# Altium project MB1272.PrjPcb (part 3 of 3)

## Sheet USB_Host_Hub&TypeC_DRP.SchDoc: USB_Host_Hub&TypeC_DRP
size A3; DocumentNumber: MB1272; Revision: A-01; SheetNumber: 6; SheetTotal: 15; Project: STM32MP15-DISCO PI
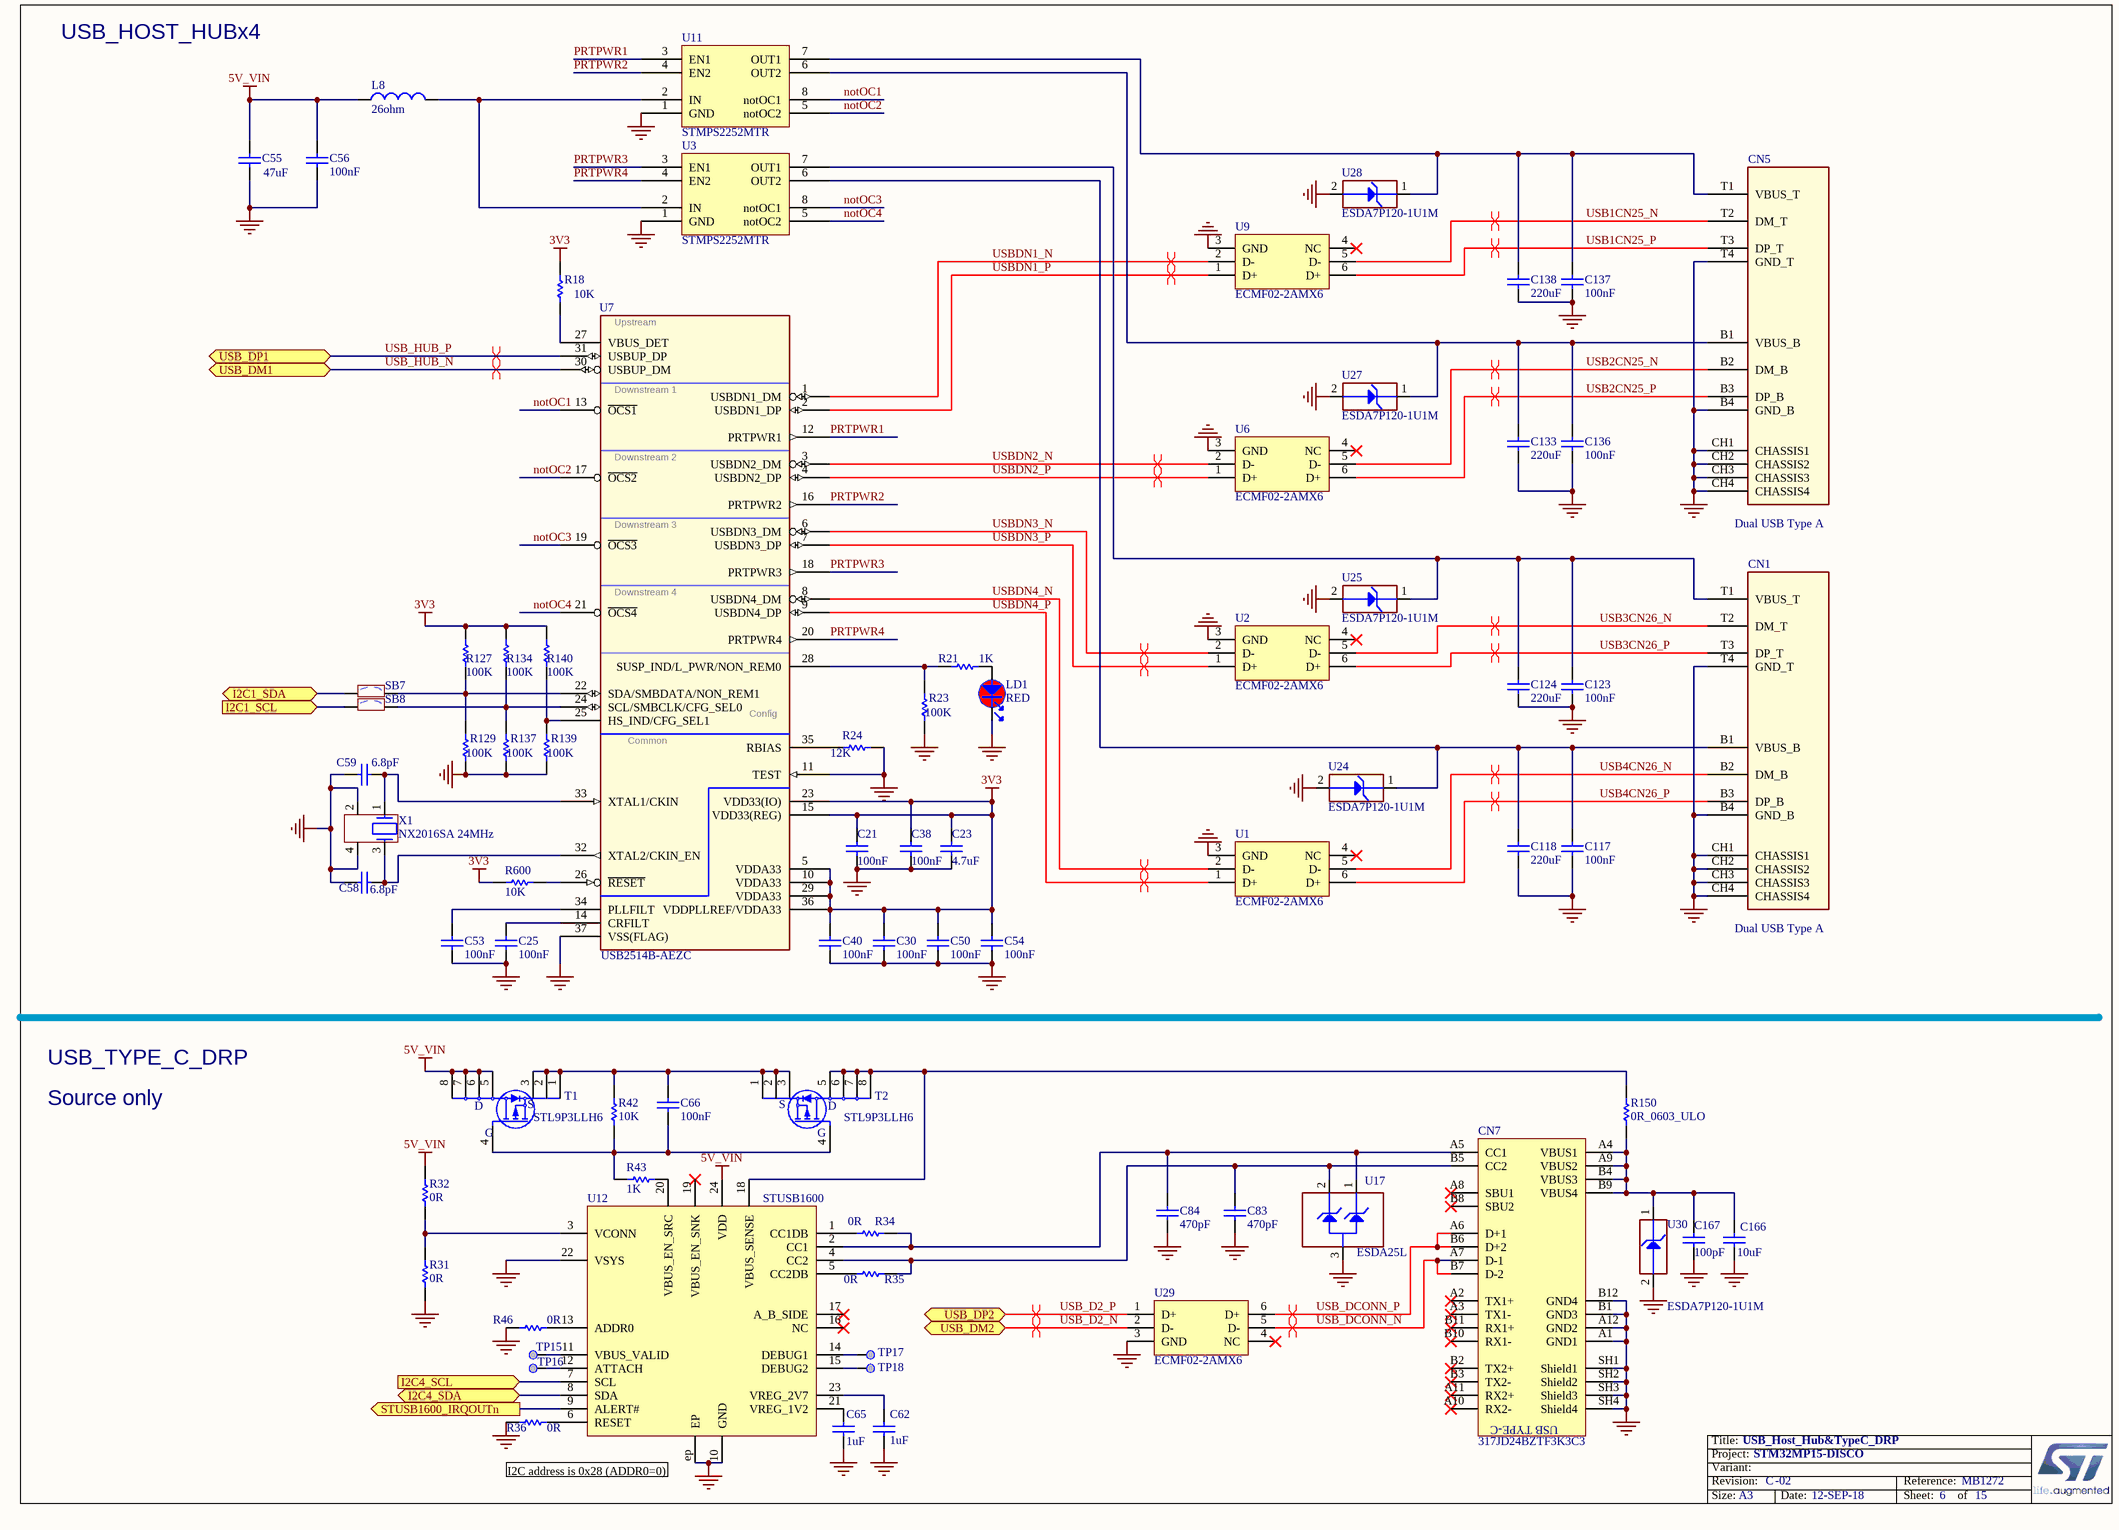
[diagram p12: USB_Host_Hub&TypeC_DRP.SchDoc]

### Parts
C21  value 100nF  [C0402]  (hidden comment: Capacitor)
C23  value 4.7uF  [C0402]  (hidden comment: Capacitor)
C25  value 100nF  [C0402]  (hidden comment: Capacitor)
C30  value 100nF  [C0402]  (hidden comment: Capacitor)
C38  value 100nF  [C0402]  (hidden comment: Capacitor)
C40  value 100nF  [C0402]  (hidden comment: Capacitor)
C50  value 100nF  [C0402]  (hidden comment: Capacitor)
C53  value 100nF  [C0402]  (hidden comment: Capacitor)
C54  value 100nF  [C0402]  (hidden comment: Capacitor)
C55  value 47uF  [C0805]  (hidden comment: Capacitor)
C56  value 100nF  [C0402]  (hidden comment: Capacitor)
C58  value 6.8pF  [C0402]  (hidden comment: Capacitor)
C59  value 6.8pF  [C0402]  (hidden comment: Capacitor)
C62  value 1uF  [C0402]  (hidden comment: Capacitor)
C65  value 1uF  [C0402]  (hidden comment: Capacitor)
C66  value 100nF  [C0402]  (hidden comment: Capacitor)
C83  value 470pF  [C0402]  (hidden comment: Capacitor)
C84  value 470pF  [C0402]  (hidden comment: Capacitor)
C117  value 100nF  [C0402]  (hidden comment: Capacitor)
C118  value 220uF  [C1206_H1P6]  (hidden comment: Capacitor)
C123  value 100nF  [C0402]  (hidden comment: Capacitor)
C124  value 220uF  [C1206_H1P6]  (hidden comment: Capacitor)
C133  value 220uF  [C1206_H1P6]  (hidden comment: Capacitor)
C136  value 100nF  [C0402]  (hidden comment: Capacitor)
C137  value 100nF  [C0402]  (hidden comment: Capacitor)
C138  value 220uF  [C1206_H1P6]  (hidden comment: Capacitor)
C166  value 10uF  [C0805]  (hidden comment: Capacitor)
C167  value 100pF  [C0402]  (hidden comment: Capacitor)
CN1  value Dual USB Type A  [CON_DUAL-USB-TYPE-A_CONEXCON_5600-3081]  (hidden comment: USB_DUAL_TYPEA_5600-3081)
CN5  value Dual USB Type A  [CON_DUAL-USB-TYPE-A_CONEXCON_5600-3081]  (hidden comment: USB_DUAL_TYPEA_5600-3081)
CN7  value 317JD24BZTF3K3C3  [CON_USB-TYPEC_COXOC_317JD24BZTF3K3C3]
L8  value 26ohm  [FIL_0603_H0P65]  (hidden comment: BEAD)
LD1  value RED  [LED_0603_RED]  (hidden comment: LED_red)
R18  value 10K  [R0402]  (hidden comment: Resistor)
R21  value 1K  [R0402]  (hidden comment: Resistor)
R23  value 100K  [R0402]  (hidden comment: Resistor)
R24  value 12K  [R0402]  (hidden comment: Resistor)
R31  value 0R  [R0402]  (hidden comment: Resistor)
R32  value 0R  [R0402]  (hidden comment: Resistor)
R34  value 0R  [R0402]  (hidden comment: Resistor)
R35  value 0R  [R0402]  (hidden comment: Resistor)
R36  value 0R  [R0402]  (hidden comment: Resistor)
R42  value 10K  [R0402]  (hidden comment: Resistor)
R43  value 1K  [R0402]  (hidden comment: Resistor)
R46  value 0R  [R0402]  (hidden comment: Resistor)
R127  value 100K  [R0402]  (hidden comment: Resistor)
R129  value 100K  [R0402]  (hidden comment: Resistor)
R134  value 100K  [R0402]  (hidden comment: Resistor)
R137  value 100K  [R0402]  (hidden comment: Resistor)
R139  value 100K  [R0402]  (hidden comment: Resistor)
R140  value 100K  [R0402]  (hidden comment: Resistor)
R150  value 0R_0603_ULO  [R0603]  (hidden comment: Resistor)
R600  value 10K  [R0402]  (hidden comment: Resistor)
SB7  SB_OFF  [SOLDER-BRIDGE_R0603-0R]  (value not drawn)
SB8  SB_OFF  [SOLDER-BRIDGE_R0603-0R]  (value not drawn)
T1  value STL9P3LLH6  [MOS_POWERFLAT_3P3X3P3_P065]
T2  value STL9P3LLH6  [MOS_POWERFLAT_3P3X3P3_P065]
TP15  Test Point  [TP_SMD_1MM]  (value not drawn)  (no BOM)
TP16  Test Point  [TP_SMD_1MM]  (value not drawn)  (no BOM)
TP17  Test Point  [TP_SMD_1MM]  (value not drawn)  (no BOM)
TP18  Test Point  [TP_SMD_1MM]  (value not drawn)  (no BOM)
U1  value ECMF02-2AMX6  [ESD_QFN-6L_1P7X1P5_P050]  (hidden comment: ​)
U2  value ECMF02-2AMX6  [ESD_QFN-6L_1P7X1P5_P050]  (hidden comment: ​)
U3  STMPS2252MTR  [ICC_SO8_5X4_P127]
U6  value ECMF02-2AMX6  [ESD_QFN-6L_1P7X1P5_P050]  (hidden comment: ​)
U7  USB2514B-AEZC  [ICC_QFN36-EPAD_6X6_P050]
U9  value ECMF02-2AMX6  [ESD_QFN-6L_1P7X1P5_P050]  (hidden comment: ​)
U11  STMPS2252MTR  [ICC_SO8_5X4_P127]
U12  value STUSB1600  [ICC_QFN24-EPAD_4X4_P050]  (hidden comment: ​Symbol correction needed ?)
U17  value ESDA25L  [ESD_SOT23]  (hidden comment: New schematic symbol : correction 2 diodes instead of one)
U24  value ESDA7P120-1U1M  [ESD_QFN1610_2N_1K_2A]  (hidden comment: ​Footprint needed DFN105P160X60-2N)
U25  value ESDA7P120-1U1M  [ESD_QFN1610_2N_1K_2A]  (hidden comment: ​Footprint needed DFN105P160X60-2N)
U27  value ESDA7P120-1U1M  [ESD_QFN1610_2N_1K_2A]  (hidden comment: ​Footprint needed DFN105P160X60-2N)
U28  value ESDA7P120-1U1M  [ESD_QFN1610_2N_1K_2A]  (hidden comment: ​Footprint needed DFN105P160X60-2N)
U29  value ECMF02-2AMX6  [ESD_QFN-6L_1P7X1P5_P050]  (hidden comment: ​)
U30  value ESDA7P120-1U1M  [ESD_QFN1610_2N_1K_2A]  (hidden comment: ​Footprint needed DFN105P160X60-2N)
X1  value NX2016SA 24MHz  [CRY_NX2016SA_4P]  (hidden comment: XTAL_4_PINS)

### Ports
I2C1_SCL (in), I2C1_SDA (bidir), I2C4_SCL (in), I2C4_SDA (bidir), STUSB1600_IRQOUTn (out), USB_DM1 (bidir), USB_DM2 (bidir), USB_DP1 (bidir), USB_DP2 (bidir)

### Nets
3V3: C21.2 C23.2 C30.2 C38.2 C40.2 C50.2 C54.2 R18.2 R127.2 R134.2 R140.2 R600.1 U7.5(VDDA33) U7.10(VDDA33) U7.15(VDD33(REG)) U7.23(VDD33(IO)) U7.29(VDDA33) U7.36(VDDPLLREF/VDDA33)
5V_VIN: C55.2 C56.2 L8.1 R32.2 T1.5(D) T1.6(D) T1.7(D) T1.8(D) U12.24(VDD)
GND: C21.1 C23.1 C25.1 C30.1 C38.1 C40.1 C50.1 C53.1 C54.1 C55.1 C56.1 C58.1 C59.1 C62.1 C65.1 C83.1 C84.1 C117.1 C118.1 C123.1 C124.1 C133.1 C136.1 C137.1 C138.1 C166.1 C167.1 CN1.B4(GND_B) CN1.CH1(CHASSIS1) CN1.CH2(CHASSIS2) CN1.CH3(CHASSIS3) CN1.CH4(CHASSIS4) CN1.T4(GND_T) CN5.B4(GND_B) CN5.CH1(CHASSIS1) CN5.CH2(CHASSIS2) CN5.CH3(CHASSIS3) CN5.CH4(CHASSIS4) CN5.T4(GND_T) CN7.A1(GND1) CN7.A12(GND2) CN7.B1(GND3) CN7.B12(GND4) CN7.SH1(Shield1) CN7.SH2(Shield2) CN7.SH3(Shield3) CN7.SH4(Shield4) LD1.2 R23.1 R24.1 R31.1 R36.1 R46.1 R129.1 R137.1 R139.1 U1.3(GND) U2.3(GND) U3.1(GND) U6.3(GND) U7.11(TEST) U7.37(VSS(FLAG)) U9.3(GND) U11.1(GND) U12.10(GND) U12.22(VSYS) U12.ep(EP) U17.3(GND) U24.2(GND) U25.2(GND) U27.2(GND) U28.2(GND) U29.3(GND) U30.2(GND) X1.2 X1.4
I2C1_SCL: SB8.1 ; port I2C1_SCL
I2C1_SDA: SB7.1 ; port I2C1_SDA
I2C4_SCL: U12.7(SCL) ; port I2C4_SCL
I2C4_SDA: U12.8(SDA) ; port I2C4_SDA
notOC1: U7.13(~{OCS1}) U11.8(notOC1)
notOC2: U7.17(~{OCS2}) U11.5(notOC2)
notOC3: U3.8(notOC1) U7.19(~{OCS3})
notOC4: U3.5(notOC2) U7.21(~{OCS4})
PRTPWR1: U7.12(PRTPWR1) U11.3(EN1)
PRTPWR2: U7.16(PRTPWR2) U11.4(EN2)
PRTPWR3: U3.3(EN1) U7.18(PRTPWR3)
PRTPWR4: U3.4(EN2) U7.20(PRTPWR4)
STUSB1600_IRQOUTn: U12.9(ALERT#) ; port STUSB1600_IRQOUTn
USB1CN25_N: CN5.T2(DM_T) U9.5(D-)
USB1CN25_P: CN5.T3(DP_T) U9.6(D+)
USB2CN25_N: CN5.B2(DM_B) U6.5(D-)
USB2CN25_P: CN5.B3(DP_B) U6.6(D+)
USB3CN26_N: CN1.T2(DM_T) U2.5(D-)
USB3CN26_P: CN1.T3(DP_T) U2.6(D+)
USB4CN26_N: CN1.B2(DM_B) U1.5(D-)
USB4CN26_P: CN1.B3(DP_B) U1.6(D+)
USB_D2_N: U29.2(D-) ; port USB_DM2  [project net USB2_N]
USB_D2_P: U29.1(D+) ; port USB_DP2  [project net USB2_P]
USB_DCONN_N: CN7.A7(D-1) CN7.B7(D-2) U29.5(D-)
USB_DCONN_P: CN7.A6(D+1) CN7.B6(D+2) U29.6(D+)
USB_HUB_N: U7.30(USBUP_DM) ; port USB_DM1  [project net USB1_N]
USB_HUB_P: U7.31(USBUP_DP) ; port USB_DP1  [project net USB1_P]
USBDN1_N: U7.1(USBDN1_DM) U9.2(D-)
USBDN1_P: U7.2(USBDN1_DP) U9.1(D+)
USBDN2_N: U6.2(D-) U7.3(USBDN2_DM)
USBDN2_P: U6.1(D+) U7.4(USBDN2_DP)
USBDN3_N: U2.2(D-) U7.6(USBDN3_DM)
USBDN3_P: U2.1(D+) U7.7(USBDN3_DP)
USBDN4_N: U1.2(D-) U7.8(USBDN4_DM)
USBDN4_P: U1.1(D+) U7.9(USBDN4_DP)
NetC25_2: C25.2 U7.14(CRFILT)
NetC53_2: C53.2 U7.34(PLLFILT)
NetC58_2: C58.2 U7.32(XTAL2/CKIN_EN) X1.3
NetC59_2: C59.2 U7.33(XTAL1/CKIN) X1.1
NetC62_2: C62.2 U12.23(VREG_2V7)
NetC65_2: C65.2 U12.21(VREG_1V2)
NetC66_1: C66.1 R42.1 R43.1 T1.4(G) T2.4(G)
NetC66_2: C66.2 R42.2 T1.1(S) T1.2(S) T1.3(S) T2.1(S) T2.2(S) T2.3(S)
NetC83_2: C83.2 CN7.B5(CC2) R35.2 U12.4(CC2) U17.2(IO2)
NetC84_2: C84.2 CN7.A5(CC1) R34.2 U12.2(CC1) U17.1(IO1)
NetC117_2: C117.2 C118.2 CN1.B1(VBUS_B) U3.6(OUT2) U24.1(IO1)
NetC123_2: C123.2 C124.2 CN1.T1(VBUS_T) U3.7(OUT1) U25.1(IO1)
NetC133_2: C133.2 C136.2 CN5.B1(VBUS_B) U11.6(OUT2) U27.1(IO1)
NetC137_2: C137.2 C138.2 CN5.T1(VBUS_T) U11.7(OUT1) U28.1(IO1)
NetC166_2: C166.2 C167.2 CN7.A4(VBUS1) CN7.A9(VBUS2) CN7.B4(VBUS3) CN7.B9(VBUS4) R150.1 U30.1(IO1)
NetL8_2: L8.2 U3.2(IN) U11.2(IN)
NetLD1_1: LD1.1 R21.1
NetR18_1: R18.1 U7.27(VBUS_DET)
NetR21_2: R21.2 R23.2 U7.28(SUSP_IND/L_PWR/NON_REM0)
NetR24_2: R24.2 U7.35(RBIAS)
NetR31_2: R31.2 R32.1 U12.3(VCONN)
NetR34_1: R34.1 U12.1(CC1DB)
NetR35_1: R35.1 U12.5(CC2DB)
NetR36_2: R36.2 U12.6(RESET)
NetR43_2: R43.2 U12.20(VBUS_EN_SRC)
NetR46_2: R46.2 U12.13(ADDR0)
NetR127_1: R127.1 R129.2 SB7.2 U7.22(SDA/SMBDATA/NON_REM1)
NetR134_1: R134.1 R137.2 SB8.2 U7.24(SCL/SMBCLK/CFG_SEL0)
NetR139_2: R139.2 R140.1 U7.25(HS_IND/CFG_SEL1)
NetR150_2: R150.2 T2.5(D) T2.6(D) T2.7(D) T2.8(D) U12.18(VBUS_SENSE)
NetR600_2: R600.2 U7.26(~{RESET})
NetTP15_1: TP15.1 U12.11(VBUS_VALID)
NetTP16_1: TP16.1 U12.12(ATTACH)
NetTP17_1: TP17.1 U12.14(DEBUG1)
NetTP18_1: TP18.1 U12.15(DEBUG2)

Not connected (* = marked no-connect by the designer): CN7 A2(TX1+)* A3(TX1-)* A8(SBU1)* A10(RX2-)* A11(RX2+)* B2(TX2+)* B3(TX2-)* B8(SBU2)* B10(RX1-)* B11(RX1+)*; U1 4(NC)*; U2 4(NC)*; U6 4(NC)*; U9 4(NC)*; U12 16(NC)* 17(A_B_SIDE)* 19(VBUS_EN_SNK)*; U29 4(NC)*

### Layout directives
differential pair: USB1_N, USB1_P, USB1CN25_N, USB1CN25_P, USB2_N, USB2_P, USB2CN25_N, USB2CN25_P, USB3CN26_N, USB3CN26_P, USB4CN26_N, USB4CN26_P, USB_DCONN_N, USB_DCONN_P, USBDN1_N, USBDN1_P, USBDN2_N, USBDN2_P, USBDN3_N, USBDN3_P, USBDN4_N, USBDN4_P

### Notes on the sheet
- USB_HOST_HUBx4
- USB_TYPE_C_DRP
- Source only
- I2C address is 0x28 (ADDR0=0)

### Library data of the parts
C21 C25 C30 C38 C40 C50 C53 C54 C56 C66 C117 C123 C136 C137 = MCD-00102: Capacitor, MLCC, 100nF, 16V, X7R, 10%, 0402, T=0,5mm; Manufacturer_Part_Number: CC0402KRX7R7BB104; Manufacturer: YAGEO; Alternate_Manufacturer: MURATA; Alternate_Manufacturer_Part_Number: GCM155R71C104KA55D; Provided_By: SUBCO; Initial_Board_Reference: MB1262
C23 = MCD-01356: Capacitor, MLCC, 4.7uF, 6V3, X5R, 20%, 0402, T=0,5mm; Manufacturer_Part_Number: GRM155R60J475ME47; Manufacturer: MURATA; Provided_By: SUBCO
C55 = MCD-00204: Capacitor, MLCC, 47uF, 10V, X5R, 20%, 0805, T=1,25mm; Manufacturer_Part_Number: GRM21BR61A476ME15K; Manufacturer: MURATA; Provided_By: SUBCO; ECCN_US: EAR99; ECCN_EU: NEC
C58 C59 = MCD-00674: Capacitor, MLCC, 6.8pF, 50V, NPO, +-0.25pF, 0402, T=0.5mm; Manufacturer_Part_Number: CC0402CRNPO9BN6R8; Manufacturer: YAGEO; Provided_By: SUBCO
C62 C65 = MCD-00095: Capacitor, MLCC, 1uF, 6V3, X5R, 10%, 0402, T=0,5mm; Manufacturer_Part_Number: GRM155R61E105KA12; Manufacturer: MURATA; Alternate_Manufacturer_Part_Number: GRM155R60J105KE19; ECCN_US: EAR99; ECCN_EU: NEC; Provided_By: SUBCO; Initial_Board_Reference: MB1262
C83 C84 = MCD-00724: Capacitor, MLCC, 470pF, 50V, NPO, 5%, 0402, T=0,5mm; Manufacturer_Part_Number: CC0402JRNPO9BN471; Manufacturer: YAGEO; Provided_By: SUBCO; Initial_Board_Reference: MB1271
C118 C124 C133 C138 = MCD-00104: Capacitor, MLCC, 220uF, 6V3, X5R, 20%, 1206, T=1,6mm; Manufacturer_Part_Number: GRM31CR60J227ME11; Manufacturer: MURATA; ECCN_US: EAR99; ECCN_EU: NEC; Provided_By: SUBCO; Initial_Board_Reference: MB1262
C166 = MCD-00014: Capacitor, MLCC, 10uF, 25V, X5R, 10%, 0805, T=0,85mm; Manufacturer_Part_Number: CC0805KRX5R8BB106; Manufacturer: YAGEO; Provided_By: SUBCO; Initial_Board_Reference: MB1274
C167 = MCD-00205: Capacitor, MLCC, 100pF, 50V, NPO, 5%, 0402, T=0,5mm; Manufacturer_Part_Number: CC0402JRNPO9BN101; Manufacturer: YAGEO; Provided_By: SUBCO
CN1 CN5 = MCD-00109: USB-Receptacle,Dual-Type-A, RA, TH, Height 15.5mm; Manufacturer: CONEXCON; Part_Type: Connector; Provided_By: SUBCO; Initial_Board_Reference: MB1262
CN7 = MCD-01108: USB tyce C certified receptacle for 1.6mm pcb height; Part_Type: Connector; Manufacturer: CHANT SINCERE (COXOC); ECCN_US: NA; Provided_By: SUBCO; Initial_Board_Reference: MB1272
L8 = MCD-00305: Bead,26R at 100Mhz,6A,0603; Manufacturer_Part_Number: BLM18KG260TN1; Manufacturer: MURATA; Part_Type: Inductor; Provided_By: SUBCO; Initial_Board_Reference: MB1272
LD1 = MCD-00049: LED, Red, 0603; Manufacturer_Part_Number: 19-213-R6C-AP1Q2B/3T; Manufacturer: EVERLIGHT; Part_Type: Display; ECCN_US: EAR99; ECCN_EU: NEC; Provided_By: SUBCO; Initial_Board_Reference: MB1274
R18 R42 R600 = MCD-00053: Resistor,10K,0402,1%,1/16W; Manufacturer_Part_Number: RC0402FR-0710KL; Manufacturer: YAGEO; Provided_By: SUBCO; Initial_Board_Reference: MB1274
R21 R43 = MCD-00061: Resistor,1K,0402,1%,1/16W; Manufacturer_Part_Number: RC0402FR-071KL; Manufacturer: YAGEO; Provided_By: SUBCO; Initial_Board_Reference: MB1274
R23 R127 R129 R134 R137 R139 R140 = MCD-00059: Resistor,100K,0402,1%,1/16W; Manufacturer_Part_Number: RC0402FR-07100KL; Manufacturer: YAGEO; Alternate_Manufacturer_Part_Number: RT0402FRE07100KL; Provided_By: SUBCO; Initial_Board_Reference: MB1274
R24 = MCD-00187: Resistor,12K,0402,1%,1/16W; Manufacturer_Part_Number: RC0402FR-0712KL; Manufacturer: YAGEO; Provided_By: SUBCO
R31 R32 R34-R36 R46 = MCD-00052: Resistor,0R,0402,5%,1/16W; Manufacturer_Part_Number: RC0402JR-070RL; Manufacturer: YAGEO; Provided_By: SUBCO; Initial_Board_Reference: MB1274
R150 = MCD-00181: Resistor,0R,0603,ULO; Manufacturer_Part_Number: PMR03EZPJ000; Manufacturer: ROHM; Provided_By: SUBCO
SB7 SB8 = MCD-00072: Solder Bridge OFF; Part_Type: Mechanical; Manufacturer: YAGEO; Manufacturer_Part_Number: RC0603JR-070RL; Provided_By: SUBCO; Initial_Board_Reference: MB1274
T1 T2 = MCD-01126: Power Mosfet, P-channel,VDS -30V,RDS 12mohm typ,ID -9A; Part_Type: IC; Manufacturer: STMICROELECTRONICS; ECCN_US: EAR99; ECCN_EU: NEC; Provided_By: SUBCO with ST control; Initial_Board_Reference: MB1272
TP15-TP18 = MCD-00074: Test Point 1mm; Part_Type: Mechanical; Initial_Board_Reference: MB1274
U1 U2 U6 U9 U29 = MCD-00649: Common mode filter with ESD protection for USB 2.0 interface; Part_Type: Diode; Manufacturer: STMICROELECTRONICS; BMS_Part_Number: 9151138; ECCN_US: EAR99; ECCN_EU: NEC; Provided_By: SUBCO with ST control; Initial_Board_Reference: MB1248
U3 U11 = MCD-00123: IC,Dual-Channel-Power-Switch,500mA,100mR,SO8; Manufacturer: STMICROELECTRONICS; BMS_Part_Number: 9159012; ECCN_US: EAR99; ECCN_EU: NEC; Provided_By: SUBCO with ST control; Initial_Board_Reference: MB1262
U7 = MCD-00145: USB HUB 2,0 Controller; Manufacturer: MICROCHIP; Part_Type: IC; ECCN_US: EAR99; ECCN_EU: NEC; Provided_By: SUBCO; Initial_Board_Reference: MB1262
U12 = MCD-00676: USB Type-C controller with VCONN switch; Part_Type: IC; Manufacturer_Part_Number: STUSB1600AQTR; Manufacturer: STMICROELECTRONICS; BMS_Part_Number: 9158053; Provided_By: SUBCO with ST control; Initial_Board_Reference: MB1272
U17 = MCD-01125: DUAL TRANSIL ARRAY FOR ESD PROTECTION; Part_Type: Diode; Manufacturer: STMICROELECTRONICS; BMS_Part_Number: 9151131; ECCN_US: EAR99; ECCN_EU: NEC; Provided_By: SUBCO with ST control; Initial_Board_Reference: MB1272
U24 U25 U27 U28 U30 = MCD-01026: High power transient voltage suppressor; Part_Type: Diode; Manufacturer: STMICROELECTRONICS; BMS_Part_Number: 9179046; ECCN_US: EAR99; ECCN_EU: NEC; Provided_By: SUBCO with ST control; Initial_Board_Reference: MB1378
X1 = MCD-01036: Crystal 24MHz, 6pF, +-20ppm, 80ohms max, SMD; Part_Type: Crystal_Osc; Manufacturer_Part_Number: NX2016SA 24MHz EXS00A-CS10820; Manufacturer: NDK; BMS_Part_Number: 9157045; Provided_By: SUBCO

## Sheet AUDIO.SchDoc: AUDIO
size A4; Author: P.A.; CompanyName: STMicroelectronics; Organization: Microcontrollers Division; Address1: 12, Rue Jules HOROWITZ; Address2: 38019 Grenoble; Address3: FRANCE; DocumentNumber: MB1272; Revision: A-01; SheetNumber: 7; SheetTotal: 15; Project: STM32MP15-DISCO PI
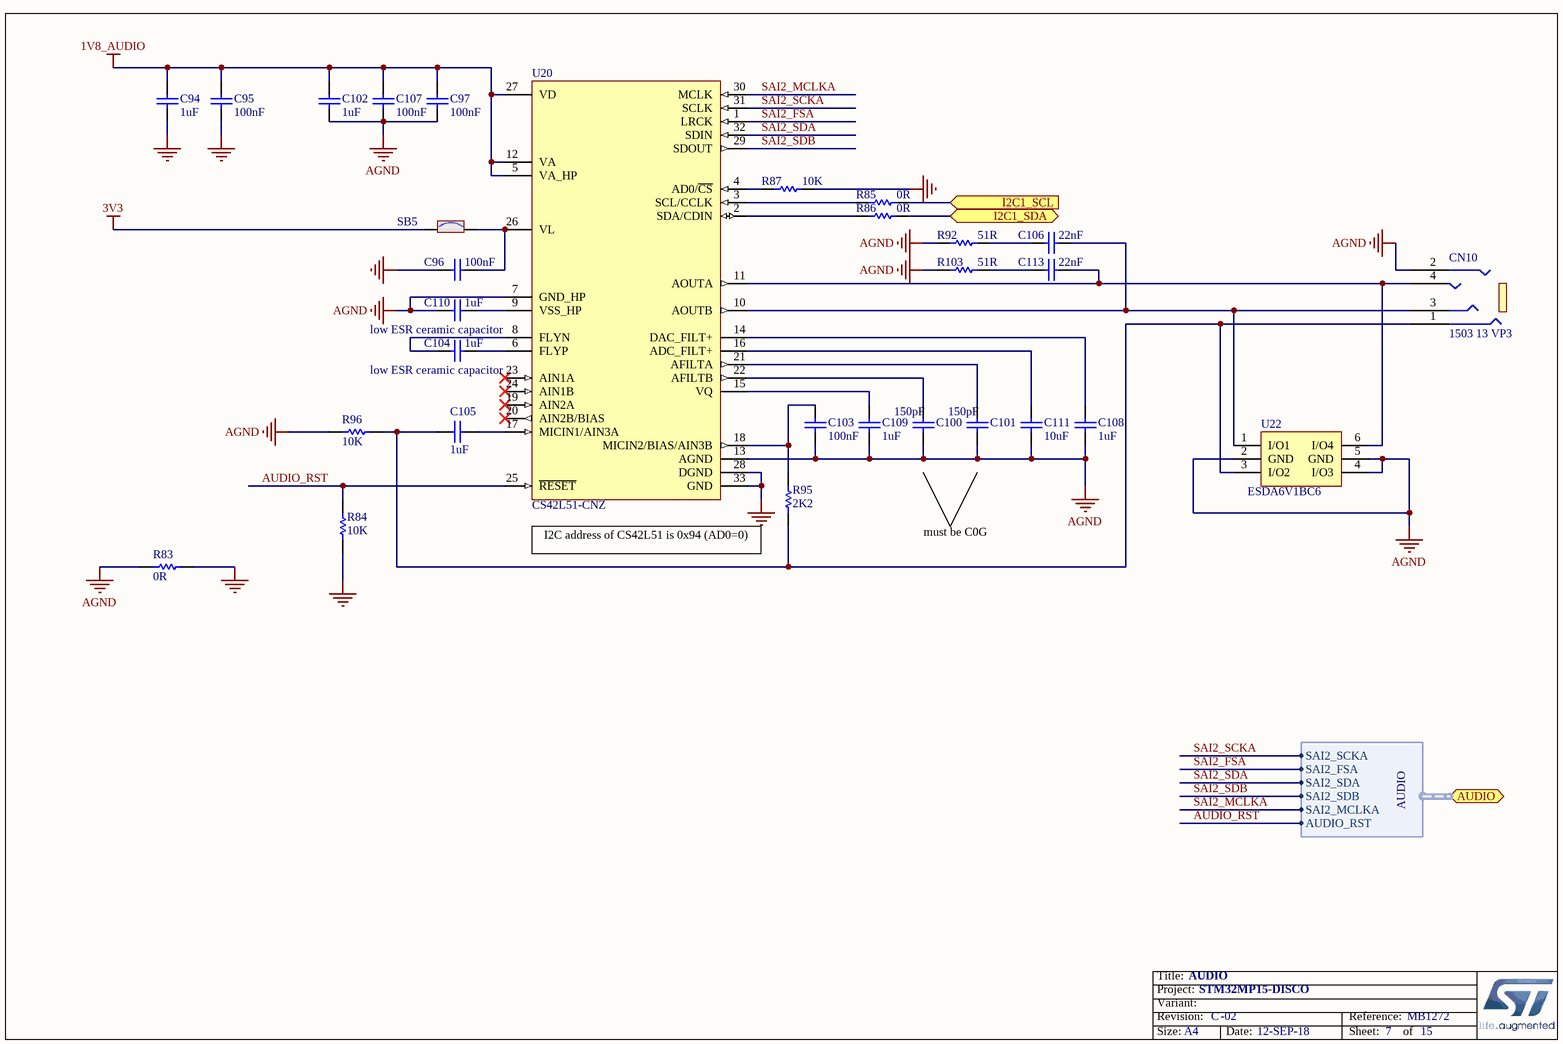
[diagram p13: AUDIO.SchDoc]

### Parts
C94  value 1uF  [C0402]
C95  value 100nF  [C0402]
C96  value 100nF  [C0402]
C97  value 100nF  [C0402]
C100  value 150pF  [C0603]
C101  value 150pF  [C0603]
C102  value 1uF  [C0402]
C103  value 100nF  [C0402]
C104  value 1uF  [C0603]
C105  value 1uF  [C0402]
C106  value 22nF  [C0402]
C107  value 100nF  [C0402]
C108  value 1uF  [C0402]
C109  value 1uF  [C0402]
C110  value 1uF  [C0603]
C111  value 10uF  [C0603]
C113  value 22nF  [C0402]
CN10  value 1503 13 VP3  [CON_JACK-3P5-SMT_LUMBERG_1503-13-VP3]
R83  value 0R  [R0603]
R84  value 10K  [R0402]
R85  value 0R  [R0402]
R86  value 0R  [R0402]
R87  value 10K  [R0402]
R92  value 51R  [R0402]
R95  value 2K2  [R0402]
R96  value 10K  [R0402]
R103  value 51R  [R0402]
SB5  (no value)  [SOLDER-BRIDGE_R0603-0R]
U20  value CS42L51-CNZ  [ICC_QFN32-EPAD_5X5_P050]
U22  value ESDA6V1BC6  [ESD_SOT23-6L]

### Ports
AUDIO (harness AUDIO), I2C1_SCL (in), I2C1_SDA (bidir)

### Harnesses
AUDIO: SAI2_SCKA, SAI2_FSA, SAI2_SDA, SAI2_SDB, SAI2_MCLKA, AUDIO_RST

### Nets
1V8_AUDIO: C94.2 C95.2 C97.2 C102.2 C107.2 U20.5(VA_HP) U20.12(VA) U20.27(VD)
3V3: SB5.1
AGND: C97.1 C100.1 C101.1 C102.1 C103.1 C107.1 C108.1 C109.1 C110.1 C111.1 CN10.2 R83.1 R92.1 R96.1 R103.1 U20.7(GND_HP) U20.13(AGND) U22.2(GND) U22.4(I/O3) U22.5(GND)
GND: C94.1 C95.1 C96.2 R83.2 R84.1 R87.2 U20.28(DGND) U20.33(GND)
AUDIO_RST: R84.2 U20.25(~{RESET}) ; port AUDIO.AUDIO_RST
I2C1_SCL: R85.2 ; port I2C1_SCL
I2C1_SDA: R86.2 ; port I2C1_SDA
SAI2_FSA: U20.1(LRCK) ; port AUDIO.SAI2_FSA
SAI2_MCLKA: U20.30(MCLK) ; port AUDIO.SAI2_MCLKA
SAI2_SCKA: U20.31(SCLK) ; port AUDIO.SAI2_SCKA
SAI2_SDA: U20.32(SDIN) ; port AUDIO.SAI2_SDA
SAI2_SDB: U20.29(SDOUT) ; port AUDIO.SAI2_SDB
NetC96_1: C96.1 SB5.2 U20.26(VL)
NetC100_2: C100.2 U20.22(AFILTB)
NetC101_2: C101.2 U20.21(AFILTA)
NetC103_2: C103.2 R95.2 U20.18(MICIN2/BIAS/AIN3B)
NetC104_1: C104.1 U20.8(FLYN)
NetC104_2: C104.2 U20.6(FLYP)
NetC105_1: C105.1 CN10.1 R95.1 R96.2 U22.3(I/O2)
NetC105_2: C105.2 U20.17(MICIN1/AIN3A)
NetC106_1: C106.1 R92.2
NetC106_2: C106.2 CN10.3 U20.10(AOUTB) U22.1(I/O1)
NetC108_2: C108.2 U20.14(DAC_FILT+)
NetC109_2: C109.2 U20.15(VQ)
NetC110_2: C110.2 U20.9(VSS_HP)
NetC111_2: C111.2 U20.16(ADC_FILT+)
NetC113_1: C113.1 R103.2
NetC113_2: C113.2 CN10.4 U20.11(AOUTA) U22.6(I/O4)
NetR85_1: R85.1 U20.3(SCL/CCLK)
NetR86_1: R86.1 U20.2(SDA/CDIN)
NetR87_1: R87.1 U20.4(AD0/~{CS})

Not connected (* = marked no-connect by the designer): U20 19(AIN2A)* 20(AIN2B/BIAS)* 23(AIN1A)* 24(AIN1B)*

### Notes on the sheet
- low ESR ceramic capacitor
- I2C address of CS42L51 is 0x94 (AD0=0)
- must be C0G

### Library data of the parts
C94 C102 C105 C108 C109 = MCD-00095: Capacitor,1uF,6V3,X5R,10%,0402; Manufacturer_Part_Number: GRM155R61E105KA12; Manufacturer: MURATA; Alternate_Manufacturer_Part_Number: GRM155R60J105KE19; ECCN_US: EAR99; ECCN_EU: NEC; Provided_By: SUBCO; Initial_Board_Reference: mb1262
C95-C97 C103 C107 = MCD-00006: Capacitor,100nF,16V,X7R,10%,0402; Manufacturer_Part_Number: CC0402KRX7R7BB104; Manufacturer: YAGEO; Alternate_Manufacturer: MURATA; Alternate_Manufacturer_Part_Number: GCM155R71C104KA55D; Provided_By: SUBCO; Initial_Board_Reference: mb1274
C100 C101 = MCD-00304: Capacitor,150pF,50V,COG,5%,0603; Manufacturer_Part_Number: CC0603JRNPO9BN151; Manufacturer: YAGEO; Provided_By: SUBCO; Initial_Board_Reference: mb1263
C104 C110 = MCD-00010: Capacitor,1uF,16V,X5R,10%,0603; Manufacturer_Part_Number: CC0603KRX5R7BB105; Manufacturer: YAGEO; Provided_By: SUBCO; Initial_Board_Reference: mb1274
C106 C113 = MCD-00202: Capacitor,22nF,16V,X7R,10%,0402; Manufacturer_Part_Number: CC0402KRX7R7BB223; Manufacturer: YAGEO; Provided_By: SUBCO
C111 = MCD-00098: Capacitor,10uF,6V3,X5R,10%,0603; Manufacturer_Part_Number: CC0603KRX5R5BB106; Manufacturer: YAGEO; Provided_By: SUBCO; Initial_Board_Reference: mb1262
CN10 = MCD-00270: Connector Jack socket Stereo 3.5mm, 4 pins, RA, SMT, Black; Manufacturer: LUMBERG; Alternate_Manufacturer: FARNELL; Alternate_Manufacturer_Part_Number: 1368640; Provided_By: SUBCO; Initial_Board_Reference: MB1272
R83 = MCD-00056: Resistor,0R,0603,5%,1/10W; Manufacturer_Part_Number: RC0603JR-070RL; Manufacturer: YAGEO; Provided_By: SUBCO; Initial_Board_Reference: mb1274
R84 R87 R96 = MCD-00053: Resistor,10K,0402,1%,1/16W; Manufacturer_Part_Number: RC0402FR-0710KL; Manufacturer: YAGEO; Provided_By: SUBCO; Initial_Board_Reference: mb1274
R85 R86 = MCD-00052: Resistor,0R,0402,5%,1/16W; Manufacturer_Part_Number: RC0402JR-070RL; Manufacturer: YAGEO; Provided_By: SUBCO; Initial_Board_Reference: mb1274
R92 R103 = MCD-00485: Resistor,51R,0402,1%,1/16W; Manufacturer_Part_Number: RC0402FR-0751RL; Manufacturer: YAGEO; Provided_By: SUBCO
R95 = MCD-00057: Resistor,2K2,0402,1%,1/16W; Manufacturer_Part_Number: RC0402FR-072K2L; Manufacturer: YAGEO; Provided_By: SUBCO; Initial_Board_Reference: mb1274
SB5 = MCD-00071: Solder Bridge ON; Part_Type: Mechanical; Manufacturer: YAGEO; Manufacturer_Part_Number: RC0603JR-070RL; Provided_By: SUBCO; Initial_Board_Reference: mb1274
U20 = MCD-00265: Low-Power, Stereo Codec with Headphone Amp; Manufacturer: CIRRUS LOGIC; Part_Type: IC; Provided_By: SUBCO; ECCN_US: EAR99; ECCN_EU: NEC; Initial_Board_Reference: MB1272
U22 = MCD-00247: Quad Bidir ESD protection; Manufacturer: STMICROELECTRONICS; Part_Type: Diode; BMS_Part_Number: 9179038; Provided_By: SUBCO with ST control; ECCN_US: EAR99; ECCN_EU: NEC; Initial_Board_Reference: MB1311

## Sheet DDR3_16bits.SchDoc: DDR3L 16 bits
size A4; Date: 30-MAR-2016; Author: F.L; CompanyName: STMicroelectronics; Organization: MCD/APPLI/HW; Address1: 12, Rue Jules HOROWITZ; Address2: 38019 Grenoble; Address3: FRANCE; DocumentNumber: MB1272; Revision: A-01; SheetNumber: 11; SheetTotal: 15; Project: STM32MP15-DISCO PI; PageSetup: Record=PageOptions¦CenterHorizontal=True¦CenterVertical=True¦PrintScale=1.39¦XCorrection=1.00¦YCorrection=1.00¦PrintKind=1¦BorderSize=5000000¦LeftOffset=0¦BottomOffset=0¦Orientation=2¦PaperLength=1000¦PaperWidth=1000¦Scale=100¦PaperSource=15¦PrintQuality=600¦MediaType=1¦DitherType=10¦PrintScaleMode=1¦PaperKind=A3¦PaperIndex=8
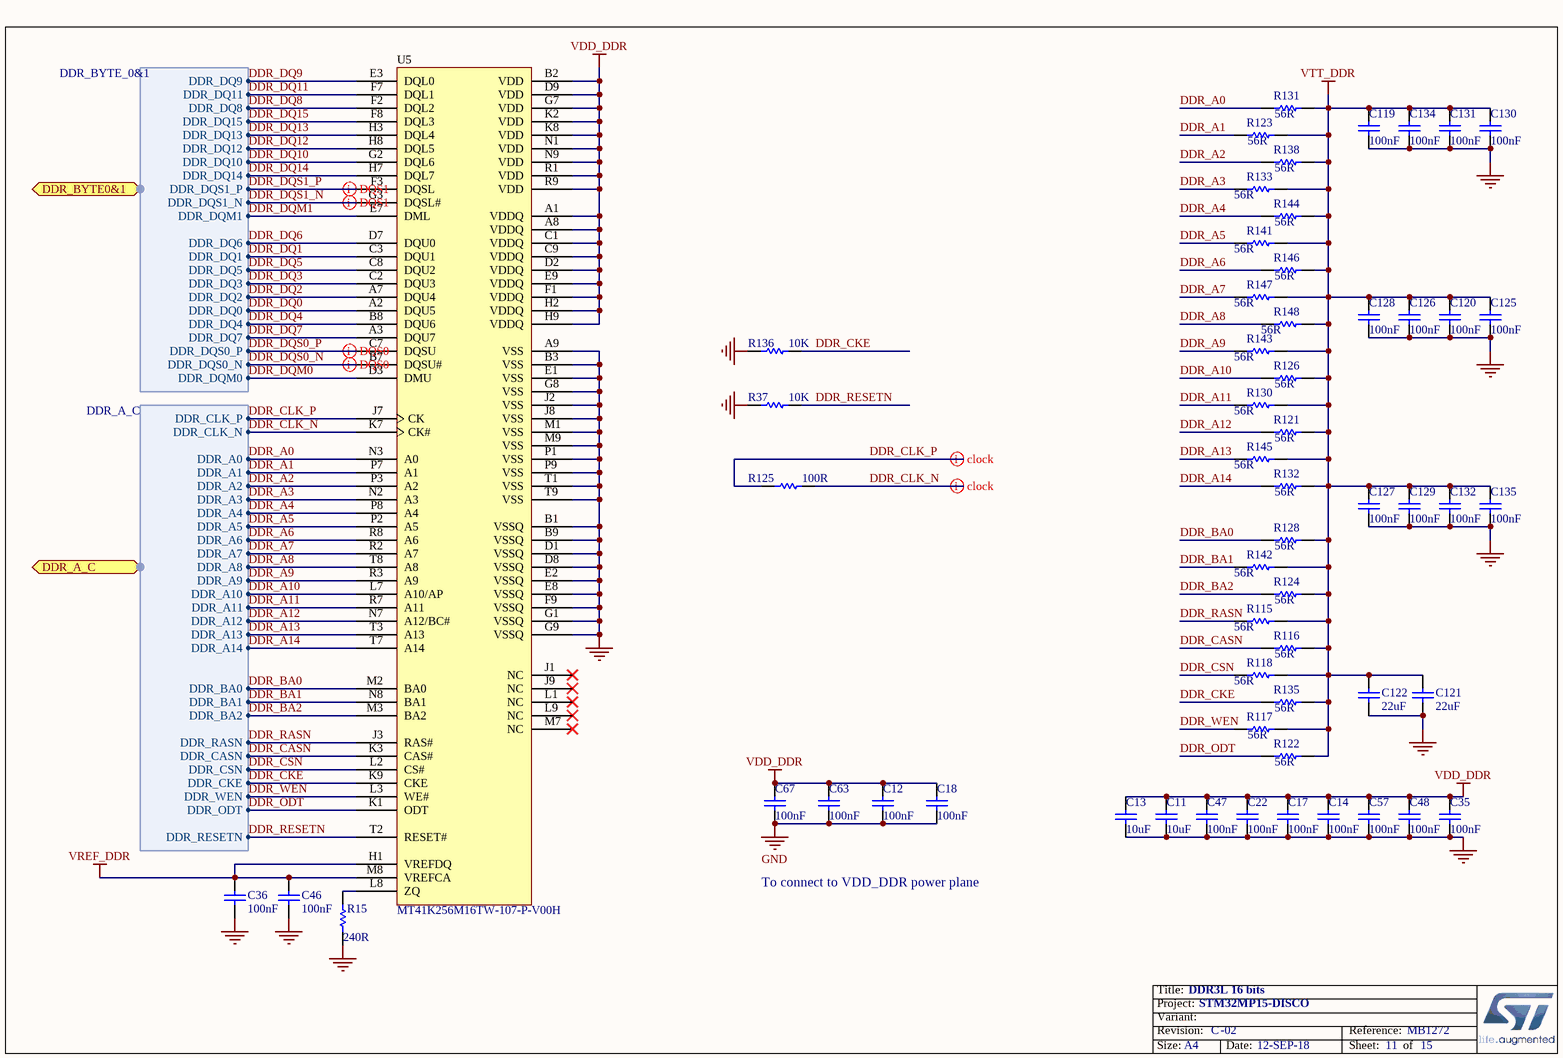
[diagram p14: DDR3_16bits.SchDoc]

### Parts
C11  value 10uF  [C0603]  (hidden comment: Capacitor)
C12  value 100nF  [C0402]  (hidden comment: Capacitor)
C13  value 10uF  [C0603]  (hidden comment: Capacitor)
C14  value 100nF  [C0402]
C17  value 100nF  [C0402]
C18  value 100nF  [C0402]  (hidden comment: Capacitor)
C22  value 100nF  [C0402]
C35  value 100nF  [C0402]
C36  value 100nF  [C0402]
C46  value 100nF  [C0402]
C47  value 100nF  [C0402]
C48  value 100nF  [C0402]
C57  value 100nF  [C0402]
C63  value 100nF  [C0402]  (hidden comment: Capacitor)
C67  value 100nF  [C0402]  (hidden comment: Capacitor)
C119  value 100nF  [C0402]
C120  value 100nF  [C0402]
C121  value 22uF  [C0603]
C122  value 22uF  [C0603]
C125  value 100nF  [C0402]
C126  value 100nF  [C0402]
C127  value 100nF  [C0402]
C128  value 100nF  [C0402]
C129  value 100nF  [C0402]
C130  value 100nF  [C0402]
C131  value 100nF  [C0402]
C132  value 100nF  [C0402]
C134  value 100nF  [C0402]
C135  value 100nF  [C0402]
R15  value 240R  [R0402]
R37  value 10K  [R0402]  (hidden comment: Resistor)
R115  value 56R  [R0402]
R116  value 56R  [R0402]
R117  value 56R  [R0402]
R118  value 56R  [R0402]
R121  value 56R  [R0402]
R122  value 56R  [R0402]
R123  value 56R  [R0402]
R124  value 56R  [R0402]
R125  value 100R  [R0402]  (hidden comment: Resistor)
R126  value 56R  [R0402]
R128  value 56R  [R0402]
R130  value 56R  [R0402]
R131  value 56R  [R0402]
R132  value 56R  [R0402]
R133  value 56R  [R0402]
R135  value 56R  [R0402]
R136  value 10K  [R0402]  (hidden comment: Resistor)
R138  value 56R  [R0402]
R141  value 56R  [R0402]
R142  value 56R  [R0402]
R143  value 56R  [R0402]
R144  value 56R  [R0402]
R145  value 56R  [R0402]
R146  value 56R  [R0402]
R147  value 56R  [R0402]
R148  value 56R  [R0402]
U5  value MT41K256M16TW-107-P-V00H  [ICC_FBGA96_8X14_P080]  (hidden comment: MT41K256M16TW-107:P - V00H)

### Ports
DDR_A_C (harness DDR_A_C), DDR_BYTE0&1 (harness DDR_BYTE_0&1)

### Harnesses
DDR_A_C: DDR_A4, DDR_A0, DDR_A2, DDR_A1, DDR_A6, DDR_A3, DDR_A5, DDR_A7, DDR_A8, DDR_A9, DDR_A14, DDR_A10, DDR_A12, DDR_A11, DDR_BA0, DDR_A13, DDR_BA1, DDR_BA2, DDR_RASN, DDR_CASN, DDR_CSN, DDR_CKE, DDR_WEN, DDR_ODT, DDR_CLK_P, DDR_CLK_N, DDR_RESETN
DDR_BYTE_0&1: DDR_DQ13, DDR_DQ9, DDR_DQ8, DDR_DQ11, DDR_DQ10, DDR_DQ15, DDR_DQ12, DDR_DQ14, DDR_DQS1_P, DDR_DQS1_N, DDR_DQ5, DDR_DQM1, DDR_DQ6, DDR_DQ2, DDR_DQ1, DDR_DQ3, DDR_DQ0, DDR_DQ4, DDR_DQ7, DDR_DQS0_P, DDR_DQS0_N, DDR_DQM0

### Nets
GND: C11.1 C12.1 C13.1 C14.2 C17.2 C18.1 C22.2 C35.2 C36.2 C46.2 C47.2 C48.2 C57.2 C63.1 C67.1 C119.2 C120.2 C121.1 C122.1 C125.2 C126.2 C127.2 C128.2 C129.2 C130.2 C131.2 C132.2 C134.2 C135.2 R15.1 R37.1 R136.1 U5.A9(VSS) U5.B1(VSSQ) U5.B3(VSS) U5.B9(VSSQ) U5.D1(VSSQ) U5.D8(VSSQ) U5.E1(VSS) U5.E2(VSSQ) U5.E8(VSSQ) U5.F9(VSSQ) U5.G1(VSSQ) U5.G8(VSS) U5.G9(VSSQ) U5.J2(VSS) U5.J8(VSS) U5.M1(VSS) U5.M9(VSS) U5.P1(VSS) U5.P9(VSS) U5.T1(VSS) U5.T9(VSS)
VDD_DDR: C11.2 C12.2 C13.2 C14.1 C17.1 C18.2 C22.1 C35.1 C47.1 C48.1 C57.1 C63.2 C67.2 U5.A1(VDDQ) U5.A8(VDDQ) U5.B2(VDD) U5.C1(VDDQ) U5.C9(VDDQ) U5.D2(VDDQ) U5.D9(VDD) U5.E9(VDDQ) U5.F1(VDDQ) U5.G7(VDD) U5.H2(VDDQ) U5.H9(VDDQ) U5.K2(VDD) U5.K8(VDD) U5.N1(VDD) U5.N9(VDD) U5.R1(VDD) U5.R9(VDD)
VREF_DDR: C36.1 C46.1 U5.H1(VREFDQ) U5.M8(VREFCA)
VTT_DDR: C119.1 C120.1 C121.2 C122.2 C125.1 C126.1 C127.1 C128.1 C129.1 C130.1 C131.1 C132.1 C134.1 C135.1 R115.2 R116.2 R117.2 R118.2 R121.2 R122.2 R123.2 R124.2 R126.2 R128.2 R130.2 R131.2 R132.2 R133.2 R135.2 R138.2 R141.2 R142.2 R143.2 R144.2 R145.2 R146.2 R147.2 R148.2
DDR_A0: R131.1 U5.N3(A0) ; port DDR_A_C.DDR_A0
DDR_A1: R123.1 U5.P7(A1) ; port DDR_A_C.DDR_A1
DDR_A2: R138.1 U5.P3(A2) ; port DDR_A_C.DDR_A2
DDR_A3: R133.1 U5.N2(A3) ; port DDR_A_C.DDR_A3
DDR_A4: R144.1 U5.P8(A4) ; port DDR_A_C.DDR_A4
DDR_A5: R141.1 U5.P2(A5) ; port DDR_A_C.DDR_A5
DDR_A6: R146.1 U5.R8(A6) ; port DDR_A_C.DDR_A6
DDR_A7: R147.1 U5.R2(A7) ; port DDR_A_C.DDR_A7
DDR_A8: R148.1 U5.T8(A8) ; port DDR_A_C.DDR_A8
DDR_A9: R143.1 U5.R3(A9) ; port DDR_A_C.DDR_A9
DDR_A10: R126.1 U5.L7(A10/AP) ; port DDR_A_C.DDR_A10
DDR_A11: R130.1 U5.R7(A11) ; port DDR_A_C.DDR_A11
DDR_A12: R121.1 U5.N7(A12/BC#) ; port DDR_A_C.DDR_A12
DDR_A13: R145.1 U5.T3(A13) ; port DDR_A_C.DDR_A13
DDR_A14: R132.1 U5.T7(A14) ; port DDR_A_C.DDR_A14
DDR_BA0: R128.1 U5.M2(BA0) ; port DDR_A_C.DDR_BA0
DDR_BA1: R142.1 U5.N8(BA1) ; port DDR_A_C.DDR_BA1
DDR_BA2: R124.1 U5.M3(BA2) ; port DDR_A_C.DDR_BA2
DDR_CASN: R116.1 U5.K3(CAS#) ; port DDR_A_C.DDR_CASN
DDR_CKE: R135.1 R136.2 U5.K9(CKE) ; port DDR_A_C.DDR_CKE
DDR_CLK_N: R125.2 U5.K7(CK#) ; port DDR_A_C.DDR_CLK_N
DDR_CLK_P: R125.1 U5.J7(CK) ; port DDR_A_C.DDR_CLK_P
DDR_CSN: R118.1 U5.L2(CS#) ; port DDR_A_C.DDR_CSN
DDR_DQ0: U5.A2(DQU5) ; port DDR_BYTE0&1.DDR_DQ0
DDR_DQ1: U5.C3(DQU1) ; port DDR_BYTE0&1.DDR_DQ1
DDR_DQ2: U5.A7(DQU4) ; port DDR_BYTE0&1.DDR_DQ2
DDR_DQ3: U5.C2(DQU3) ; port DDR_BYTE0&1.DDR_DQ3
DDR_DQ4: U5.B8(DQU6) ; port DDR_BYTE0&1.DDR_DQ4
DDR_DQ5: U5.C8(DQU2) ; port DDR_BYTE0&1.DDR_DQ5
DDR_DQ6: U5.D7(DQU0) ; port DDR_BYTE0&1.DDR_DQ6
DDR_DQ7: U5.A3(DQU7) ; port DDR_BYTE0&1.DDR_DQ7
DDR_DQ8: U5.F2(DQL2) ; port DDR_BYTE0&1.DDR_DQ8
DDR_DQ9: U5.E3(DQL0) ; port DDR_BYTE0&1.DDR_DQ9
DDR_DQ10: U5.G2(DQL6) ; port DDR_BYTE0&1.DDR_DQ10
DDR_DQ11: U5.F7(DQL1) ; port DDR_BYTE0&1.DDR_DQ11
DDR_DQ12: U5.H8(DQL5) ; port DDR_BYTE0&1.DDR_DQ12
DDR_DQ13: U5.H3(DQL4) ; port DDR_BYTE0&1.DDR_DQ13
DDR_DQ14: U5.H7(DQL7) ; port DDR_BYTE0&1.DDR_DQ14
DDR_DQ15: U5.F8(DQL3) ; port DDR_BYTE0&1.DDR_DQ15
DDR_DQM0: U5.D3(DMU) ; port DDR_BYTE0&1.DDR_DQM0
DDR_DQM1: U5.E7(DML) ; port DDR_BYTE0&1.DDR_DQM1
DDR_DQS0_N: U5.B7(DQSU#) ; port DDR_BYTE0&1.DDR_DQS0_N
DDR_DQS0_P: U5.C7(DQSU) ; port DDR_BYTE0&1.DDR_DQS0_P
DDR_DQS1_N: U5.G3(DQSL#) ; port DDR_BYTE0&1.DDR_DQS1_N
DDR_DQS1_P: U5.F3(DQSL) ; port DDR_BYTE0&1.DDR_DQS1_P
DDR_ODT: R122.1 U5.K1(ODT) ; port DDR_A_C.DDR_ODT
DDR_RASN: R115.1 U5.J3(RAS#) ; port DDR_A_C.DDR_RASN
DDR_RESETN: R37.2 U5.T2(RESET#) ; port DDR_A_C.DDR_RESETN
DDR_WEN: R117.1 U5.L3(WE#) ; port DDR_A_C.DDR_WEN
NetR15_2: R15.2 U5.L8(ZQ)

Not connected (* = marked no-connect by the designer): U5 J1(NC)* J9(NC)* L1(NC)* L9(NC)* M7(NC)*

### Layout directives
differential pair: DDR_CLK_N, DDR_CLK_P, DDR_DQS0_N, DDR_DQS0_P, DDR_DQS1_N, DDR_DQS1_P

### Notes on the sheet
- To connect to VDD_DDR power plane

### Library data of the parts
C11 C13 = MCD-00099: Capacitor, MLCC, 10uF, 10V, X5R, 10%, 0603, T=0,8mm; Manufacturer_Part_Number: GRM188R61A106KE69D; Manufacturer: MURATA; ECCN_US: EAR99; ECCN_EU: NEC; Provided_By: SUBCO; Initial_Board_Reference: MB1262
C12 C18 C63 C67 = MCD-00006: Capacitor, MLCC, 100nF, 16V, X7R, 10%, 0402, T=0.5mm; Manufacturer_Part_Number: CC0402KRX7R7BB104; Manufacturer: YAGEO; Alternate_Manufacturer: MURATA; Alternate_Manufacturer_Part_Number: GCM155R71C104KA55D; Provided_By: SUBCO; Initial_Board_Reference: MB1274
C14 C17 C22 C35 C36 C46-C48 C57 C119 C120 C125-C132 C134 C135 = MCD-00006: as C95-C97 on sheet AUDIO
C121 C122 = MCD-00100: Capacitor, MLCC, 22uF, 6V3, X5R, 20%, 0603, T=0,8mm; Manufacturer_Part_Number: GRM188R60J226MEA0J; Manufacturer: MURATA; ECCN_US: EAR99; ECCN_EU: NEC; Provided_By: SUBCO; Initial_Board_Reference: mb1262
R15 = MCD-00120: Resistor,240R,0402,1%,1/16W; Manufacturer_Part_Number: RC0402FR-07240RL; Manufacturer: YAGEO; Provided_By: SUBCO; Initial_Board_Reference: mb1262
R37 R136 = MCD-00053: as R18 on sheet USB_Host_Hub&TypeC_DRP
R115-R118 R121-R124 R126 R128 R130-R133 R135 R138 R141-R148 = MCD-00118: Resistor,56R,0402,1%,1/16W; Manufacturer_Part_Number: RC0402FR-0756RL; Manufacturer: YAGEO; Provided_By: SUBCO; Initial_Board_Reference: mb1262
R125 = MCD-00067: Resistor,100R,0402,1%,1/16W; Manufacturer_Part_Number: RC0402FR-07100RL; Manufacturer: YAGEO; Provided_By: SUBCO; Initial_Board_Reference: MB1274
U5 = MCD-00207: Memory,DDR3L,4Gb,256Mbx16,1866MT/s,1V35,FBGA96; Part_Type: IC; Manufacturer: MICRON; Provided_By: SUBCO; Initial_Board_Reference: MB1263

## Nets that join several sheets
1V2_HDMI: Power_PMIC (C31.2 U4.21), HDMI (5 pins)
1V8_AUDIO: Power_PMIC (C33.2 U4.23), AUDIO (8 pins)
3V3: Power_PMIC (5 pins), MPU_12x12 (6 pins), Peripherals (10 pins), ST_LINK_V2-1 (R94.1), GPIO_&_Arduino_ Connectors (5 pins), DSI_LCD (L7.1 R11.1), WLAN_BLUETOOTH (10 pins), Ethernet (L10.2 L11.2), USB_Host_Hub&TypeC_DRP (18 pins), AUDIO (SB5.1)
3V3_HDMI: Power_PMIC (C20.2 U4.18), HDMI (R154.2)
5V_VIN: Power_PMIC (20 pins), ST_LINK_V2-1 (D1.1), GPIO_&_Arduino_ Connectors (CN2.2 CN2.4 R165.1 U23.1), HDMI (F1.1 R97.2 R98.2), USB_Host_Hub&TypeC_DRP (9 pins)
GND: Power_PMIC (51 pins), Power_MPU (85 pins), MPU_12x12 (15 pins), Peripherals (16 pins), ST_LINK_V2-1 (35 pins), GPIO_&_Arduino_ Connectors (15 pins), DSI_LCD (12 pins), WLAN_BLUETOOTH (22 pins), Ethernet (33 pins), HDMI (36 pins), USB_Host_Hub&TypeC_DRP (76 pins), AUDIO (8 pins), DDR3_16bits (53 pins)
VDD: Power_PMIC (C44.2 L6.2 U4.31 U4.42), Power_MPU (16 pins), MPU_12x12 (5 pins), Peripherals (R101.2 R102.2 R109.2)
VDD_CORE: Power_PMIC (LNK2.2 R3.2), Power_MPU (28 pins)
VDD_DDR: Power_PMIC (5 pins), Power_MPU (14 pins), DDR3_16bits (31 pins)
VDD_USB: Power_PMIC (C16.2 U4.39), Power_MPU (C139.2 U13.AA15 U13.AA17)
VDDA: Power_PMIC (C32.2 U4.20), Power_MPU (R78.1)
VREF+: Power_MPU (C165.2 R74.2 U13.R4), GPIO_&_Arduino_ Connectors (C1.2 R4.2)
VREF_DDR: Power_PMIC (C15.2 U4.16), MPU_12x12 (C68.2 U13.AC20), DDR3_16bits (C36.1 C46.1 U5.H1 U5.M8)
VTT_DDR: Power_PMIC (C9.2 U4.14), DDR3_16bits (38 pins)
ARD_A0: MPU_12x12 (U13.AC4), GPIO_&_Arduino_ Connectors (CN17.1)
ARD_A1: MPU_12x12 (U13.Y5), GPIO_&_Arduino_ Connectors (CN17.2)
ARD_A2: MPU_12x12 (U13.U3), GPIO_&_Arduino_ Connectors (CN17.3)
ARD_A3: MPU_12x12 (U13.U4), GPIO_&_Arduino_ Connectors (CN17.4)
ARD_A4: MPU_12x12 (U13.W2), GPIO_&_Arduino_ Connectors (SB24.1)
ARD_A5: MPU_12x12 (U13.Y9), GPIO_&_Arduino_ Connectors (SB26.1)
ARD_D0: MPU_12x12 (U13.AA11), GPIO_&_Arduino_ Connectors (CN14.1)
ARD_D1: MPU_12x12 (U13.AC13), GPIO_&_Arduino_ Connectors (CN14.2)
ARD_D2: MPU_12x12 (U13.C8), GPIO_&_Arduino_ Connectors (CN14.3)
ARD_D3: MPU_12x12 (U13.L3), GPIO_&_Arduino_ Connectors (CN14.4)
ARD_D4: MPU_12x12 (U13.Y15), GPIO_&_Arduino_ Connectors (CN14.5)
ARD_D5: MPU_12x12 (U13.J2), GPIO_&_Arduino_ Connectors (CN14.6)
ARD_D6: MPU_12x12 (U13.AA9), GPIO_&_Arduino_ Connectors (CN14.7)
ARD_D7: MPU_12x12 (U13.B9), GPIO_&_Arduino_ Connectors (CN14.8)
ARD_D8: MPU_12x12 (U13.T4), GPIO_&_Arduino_ Connectors (CN13.1)
ARD_D9: MPU_12x12 (U13.Y11), GPIO_&_Arduino_ Connectors (CN13.2)
ARD_D10: MPU_12x12 (U13.A4), GPIO_&_Arduino_ Connectors (CN13.3)
ARD_D11: MPU_12x12 (U13.C6), GPIO_&_Arduino_ Connectors (CN13.4)
ARD_D12: MPU_12x12 (U13.A3), GPIO_&_Arduino_ Connectors (CN13.5)
ARD_D13: MPU_12x12 (U13.B4), GPIO_&_Arduino_ Connectors (CN13.6 SB6.1)
ARD_D14: MPU_12x12 (R166.2 U13.AB19), GPIO_&_Arduino_ Connectors (CN2.3 CN13.9 SB23.1)
ARD_D15: MPU_12x12 (R167.2 U13.AA18), GPIO_&_Arduino_ Connectors (CN2.5 CN13.10 SB25.1)
AUDIO_RST: MPU_12x12 (U13.Y13), AUDIO (R84.2 U20.25)
BOOT0: MPU_12x12 (U13.N1), Peripherals (SW1.1)
BOOT1: MPU_12x12 (U13.N4), Peripherals (R82.2)
BOOT2: MPU_12x12 (U13.M2), Peripherals (SW1.2)
BT_DEV_WAKE: MPU_12x12 (U13.J3), WLAN_BLUETOOTH (U8.39)
BT_HOST_WAKE: MPU_12x12 (U13.A2), WLAN_BLUETOOTH (U8.38)
BT_PCM_CLK: MPU_12x12 (U13.G3), WLAN_BLUETOOTH (U8.11)
BT_PCM_SDI: MPU_12x12 (U13.G1), WLAN_BLUETOOTH (U8.10)
BT_PCM_SDO: MPU_12x12 (U13.J4), WLAN_BLUETOOTH (U8.9)
BT_PCM_WS: MPU_12x12 (U13.G4), WLAN_BLUETOOTH (U8.8)
BT_REG_ON: MPU_12x12 (U13.H1), WLAN_BLUETOOTH (TP29.1 U8.14)
DDR_A0: MPU_12x12 (U13.L20), DDR3_16bits (R131.1 U5.N3)
DDR_A1: MPU_12x12 (U13.P22), DDR3_16bits (R123.1 U5.P7)
DDR_A2: MPU_12x12 (U13.J20), DDR3_16bits (R138.1 U5.P3)
DDR_A3: MPU_12x12 (U13.K22), DDR3_16bits (R133.1 U5.N2)
DDR_A4: MPU_12x12 (U13.V20), DDR3_16bits (R144.1 U5.P8)
DDR_A5: MPU_12x12 (U13.H20), DDR3_16bits (R141.1 U5.P2)
DDR_A6: MPU_12x12 (U13.W20), DDR3_16bits (R146.1 U5.R8)
DDR_A7: MPU_12x12 (U13.E20), DDR3_16bits (R147.1 U5.R2)
DDR_A8: MPU_12x12 (U13.Y20), DDR3_16bits (R148.1 U5.T8)
DDR_A9: MPU_12x12 (U13.G20), DDR3_16bits (R143.1 U5.R3)
DDR_A10: MPU_12x12 (U13.R22), DDR3_16bits (R126.1 U5.L7)
DDR_A11: MPU_12x12 (U13.R20), DDR3_16bits (R130.1 U5.R7)
DDR_A12: MPU_12x12 (U13.P23), DDR3_16bits (R121.1 U5.N7)
DDR_A13: MPU_12x12 (U13.F20), DDR3_16bits (R145.1 U5.T3)
DDR_A14: MPU_12x12 (U13.R21), DDR3_16bits (R132.1 U5.T7)
DDR_BA0: MPU_12x12 (U13.L23), DDR3_16bits (R128.1 U5.M2)
DDR_BA1: MPU_12x12 (U13.U20), DDR3_16bits (R142.1 U5.N8)
DDR_BA2: MPU_12x12 (U13.M21), DDR3_16bits (R124.1 U5.M3)
DDR_CASN: MPU_12x12 (U13.N20), DDR3_16bits (R116.1 U5.K3)
DDR_CKE: MPU_12x12 (U13.T20), DDR3_16bits (R135.1 R136.2 U5.K9)
DDR_CLK_N: MPU_12x12 (U13.N23), DDR3_16bits (R125.2 U5.K7)
DDR_CLK_P: MPU_12x12 (U13.N22), DDR3_16bits (R125.1 U5.J7)
DDR_CSN: MPU_12x12 (U13.M22), DDR3_16bits (R118.1 U5.L2)
DDR_DQ0: MPU_12x12 (U13.E22), DDR3_16bits (U5.A2)
DDR_DQ1: MPU_12x12 (U13.F22), DDR3_16bits (U5.C3)
DDR_DQ2: MPU_12x12 (U13.H21), DDR3_16bits (U5.A7)
DDR_DQ3: MPU_12x12 (U13.E21), DDR3_16bits (U5.C2)
DDR_DQ4: MPU_12x12 (U13.J21), DDR3_16bits (U5.B8)
DDR_DQ5: MPU_12x12 (U13.J22), DDR3_16bits (U5.C8)
DDR_DQ6: MPU_12x12 (U13.H22), DDR3_16bits (U5.D7)
DDR_DQ7: MPU_12x12 (U13.G21), DDR3_16bits (U5.A3)
DDR_DQ8: MPU_12x12 (U13.T21), DDR3_16bits (U5.F2)
DDR_DQ9: MPU_12x12 (U13.U21), DDR3_16bits (U5.E3)
DDR_DQ10: MPU_12x12 (U13.T22), DDR3_16bits (U5.G2)
DDR_DQ11: MPU_12x12 (U13.W21), DDR3_16bits (U5.F7)
DDR_DQ12: MPU_12x12 (U13.W23), DDR3_16bits (U5.H8)
DDR_DQ13: MPU_12x12 (U13.T23), DDR3_16bits (U5.H3)
DDR_DQ14: MPU_12x12 (U13.W22), DDR3_16bits (U5.H7)
DDR_DQ15: MPU_12x12 (U13.Y21), DDR3_16bits (U5.F8)
DDR_DQM0: MPU_12x12 (U13.H23), DDR3_16bits (U5.D3)
DDR_DQM1: MPU_12x12 (U13.V22), DDR3_16bits (U5.E7)
DDR_DQS0_N: MPU_12x12 (U13.G23), DDR3_16bits (U5.B7)
DDR_DQS0_P: MPU_12x12 (U13.G22), DDR3_16bits (U5.C7)
DDR_DQS1_N: MPU_12x12 (U13.U23), DDR3_16bits (U5.G3)
DDR_DQS1_P: MPU_12x12 (U13.U22), DDR3_16bits (U5.F3)
DDR_ODT: MPU_12x12 (U13.L22), DDR3_16bits (R122.1 U5.K1)
DDR_RASN: MPU_12x12 (U13.N21), DDR3_16bits (R115.1 U5.J3)
DDR_RESETN: MPU_12x12 (U13.D20), DDR3_16bits (R37.2 U5.T2)
DDR_WEN: MPU_12x12 (U13.M20), DDR3_16bits (R117.1 U5.L3)
DSI_CK_N: MPU_12x12 (U13.A16), DSI_LCD (CN4.5)
DSI_CK_P: MPU_12x12 (U13.B16), DSI_LCD (CN4.6)
DSI_D0_N: MPU_12x12 (U13.B15), DSI_LCD (CN4.8)
DSI_D0_P: MPU_12x12 (U13.C15), DSI_LCD (CN4.9)
DSI_D1_N: MPU_12x12 (U13.A17), DSI_LCD (CN4.2)
DSI_D1_P: MPU_12x12 (U13.B17), DSI_LCD (CN4.3)
DSI_LCD_BL_CTRL: MPU_12x12 (U13.C19), DSI_LCD (CN4.19)
DSI_LCD_INT: MPU_12x12 (U13.A14), DSI_LCD (CN4.17)
DSI_RESET: MPU_12x12 (U13.D19), DSI_LCD (CN4.20 R11.2)
DSI_TE: MPU_12x12 (U13.B14), DSI_LCD (CN4.18)
ETH_CLK: MPU_12x12 (U13.Y8), Ethernet (R69.2)
ETH_CLK125: MPU_12x12 (U13.Y6), Ethernet (R153.1)
ETH_GTX_CLK: MPU_12x12 (U13.AB2), Ethernet (U18.20)
ETH_MDC: MPU_12x12 (U13.AA6), Ethernet (R76.1 U18.13)
ETH_MDINT: MPU_12x12 (U13.AC8), Ethernet (R65.1 U18.31)
ETH_MDIO: MPU_12x12 (U13.AC3), Ethernet (R75.1 U18.14)
ETH_NRST: MPU_12x12 (R300.2 U13.AC2), Ethernet (U18.12)
ETH_RX_CLK: MPU_12x12 (U13.AA4), Ethernet (R50.2 R58.1)
ETH_RX_DV: MPU_12x12 (U13.AB8), Ethernet (R51.2 R59.1)
ETH_RXD0: MPU_12x12 (U13.AC7), Ethernet (R52.1 R60.1)
ETH_RXD1: MPU_12x12 (U13.AB7), Ethernet (R53.1 R61.1)
ETH_RXD2: MPU_12x12 (U13.AB6), Ethernet (R54.2 R62.1)
ETH_RXD3: MPU_12x12 (U13.AA7), Ethernet (R55.1 R63.1)
ETH_TX_EN: MPU_12x12 (U13.AB1), Ethernet (U18.19)
ETH_TXD0: MPU_12x12 (U13.AA2), Ethernet (U18.18)
ETH_TXD1: MPU_12x12 (U13.AA1), Ethernet (U18.17)
ETH_TXD2: MPU_12x12 (U13.Y2), Ethernet (U18.16)
ETH_TXD3: MPU_12x12 (U13.Y1), Ethernet (U18.15)
EXP_GPIO4: MPU_12x12 (TP19.1 U13.A13), GPIO_&_Arduino_ Connectors (CN2.7)
EXP_GPIO5: MPU_12x12 (TP1.1 U13.V2), GPIO_&_Arduino_ Connectors (CN2.29)
EXP_GPIO6: MPU_12x12 (U13.C4), GPIO_&_Arduino_ Connectors (CN2.31)
EXP_GPIO7: MPU_12x12 (U13.U1), GPIO_&_Arduino_ Connectors (CN2.26)
EXP_GPIO8: MPU_12x12 (U13.AA13), GPIO_&_Arduino_ Connectors (CN2.24)
EXP_GPIO9: MPU_12x12 (U13.AC11), GPIO_&_Arduino_ Connectors (CN2.21)
EXP_GPIO10: MPU_12x12 (U13.AA14), GPIO_&_Arduino_ Connectors (CN2.19)
EXP_GPIO11: MPU_12x12 (U13.AB12), GPIO_&_Arduino_ Connectors (CN2.23)
EXP_GPIO12: MPU_12x12 (U13.AA19), GPIO_&_Arduino_ Connectors (CN2.32)
EXP_GPIO13: MPU_12x12 (U13.B11), GPIO_&_Arduino_ Connectors (CN2.33)
EXP_GPIO14: MPU_12x12 (U13.Y3), GPIO_&_Arduino_ Connectors (CN2.8)
EXP_GPIO15: MPU_12x12 (U13.AC5), GPIO_&_Arduino_ Connectors (CN2.10)
EXP_GPIO16: MPU_12x12 (U13.AA10), GPIO_&_Arduino_ Connectors (CN2.36)
EXP_GPIO17: MPU_12x12 (U13.AB9), GPIO_&_Arduino_ Connectors (CN2.11)
EXP_GPIO18: MPU_12x12 (SB14.1), GPIO_&_Arduino_ Connectors (CN2.12)
EXP_GPIO19: MPU_12x12 (SB16.1), GPIO_&_Arduino_ Connectors (CN2.35)
EXP_GPIO20: MPU_12x12 (SB15.1), GPIO_&_Arduino_ Connectors (CN2.38)
EXP_GPIO21: MPU_12x12 (SB13.1), GPIO_&_Arduino_ Connectors (CN2.40)
EXP_GPIO22: MPU_12x12 (U13.B7), GPIO_&_Arduino_ Connectors (CN2.15)
EXP_GPIO23: MPU_12x12 (U13.A5), GPIO_&_Arduino_ Connectors (CN2.16)
EXP_GPIO24: MPU_12x12 (U13.D8), GPIO_&_Arduino_ Connectors (CN2.18)
EXP_GPIO25: MPU_12x12 (U13.D9), GPIO_&_Arduino_ Connectors (CN2.22)
EXP_GPIO26: MPU_12x12 (U13.D7), GPIO_&_Arduino_ Connectors (CN2.37)
EXP_GPIO27: MPU_12x12 (U13.D10), GPIO_&_Arduino_ Connectors (CN2.13)
HDMI_CEC: MPU_12x12 (U13.Y14), HDMI (U14.50)
HDMI_INT: MPU_12x12 (U13.W1), HDMI (U14.52)
HDMI_NRST: MPU_12x12 (R40.2 U13.Y17), HDMI (U14.51)
I2C1_SCL: MPU_12x12 (R1.2 U13.Y18), GPIO_&_Arduino_ Connectors (CN2.28), DSI_LCD (CN4.11), HDMI (U14.1), USB_Host_Hub&TypeC_DRP (SB8.1), AUDIO (R85.2)
I2C1_SDA: MPU_12x12 (R2.2 U13.Y4), GPIO_&_Arduino_ Connectors (CN2.27), DSI_LCD (CN4.12), HDMI (U14.2), USB_Host_Hub&TypeC_DRP (SB7.1), AUDIO (R86.2)
I2C4_SCL: Power_PMIC (U4.4), MPU_12x12 (R5.2 U13.G2), USB_Host_Hub&TypeC_DRP (U12.7)
I2C4_SDA: Power_PMIC (U4.3), MPU_12x12 (R7.2 U13.H2), USB_Host_Hub&TypeC_DRP (U12.8)
I2S2_CK: MPU_12x12 (U13.A8), HDMI (U14.45)
I2S2_SDO: MPU_12x12 (U13.E1), HDMI (U14.41)
I2S2_WS: MPU_12x12 (U13.B10), HDMI (U14.44)
JTDO_TRACESWO: MPU_12x12 (TP8.1 U13.A19), ST_LINK_V2-1 (SB19.2)
LED_B: MPU_12x12 (U13.AC10), Peripherals (R108.1)
LED_Y: MPU_12x12 (U13.W4), Peripherals (R107.1)
LPO_32: MPU_12x12 (U13.L4), WLAN_BLUETOOTH (TP26.1 U8.37)
LTDC_B0: MPU_12x12 (U13.K1), HDMI (U14.32)
LTDC_B1: MPU_12x12 (U13.K4), HDMI (U14.31)
LTDC_B2: MPU_12x12 (U13.AB11), HDMI (U14.30)
LTDC_B3: MPU_12x12 (U13.B5), HDMI (U14.29)
LTDC_B4: MPU_12x12 (U13.E4), HDMI (U14.28)
LTDC_B5: MPU_12x12 (U13.U2), HDMI (U14.27)
LTDC_B6: MPU_12x12 (U13.AB10), HDMI (U14.25)
LTDC_B7: MPU_12x12 (U13.K3), HDMI (U14.24)
LTDC_CLK: MPU_12x12 (U13.AC14), HDMI (U14.22)
LTDC_DE: MPU_12x12 (U13.Y12), HDMI (U14.33)
LTDC_G0: MPU_12x12 (U13.C11), HDMI (U14.23)
LTDC_G1: MPU_12x12 (U13.C10), HDMI (U14.20)
LTDC_G2: MPU_12x12 (U13.D1), HDMI (U14.19)
LTDC_G3: MPU_12x12 (U13.C3), HDMI (U14.18)
LTDC_G4: MPU_12x12 (U13.B1), HDMI (U14.17)
LTDC_G5: MPU_12x12 (U13.C1), HDMI (U14.16)
LTDC_G6: MPU_12x12 (U13.E3), HDMI (U14.15)
LTDC_G7: MPU_12x12 (U13.E2), HDMI (U14.14)
LTDC_HSYNC: MPU_12x12 (U13.T1), HDMI (U14.34)
LTDC_R0: MPU_12x12 (U13.AB4), HDMI (U14.13)
LTDC_R1: MPU_12x12 (U13.AA3), HDMI (U14.11)
LTDC_R2: MPU_12x12 (U13.D5), HDMI (U14.10)
LTDC_R3: MPU_12x12 (U13.C5), HDMI (U14.9)
LTDC_R4: MPU_12x12 (U13.C2), HDMI (U14.8)
LTDC_R5: MPU_12x12 (U13.AB5), HDMI (U14.7)
LTDC_R6: MPU_12x12 (U13.B2), HDMI (U14.6)
LTDC_R7: MPU_12x12 (U13.D3), HDMI (U14.4)
LTDC_VSYNC: MPU_12x12 (U13.H4), HDMI (U14.35)
NRST: Power_PMIC (R6.1), MPU_12x12 (U13.M3), Peripherals (5 pins), ST_LINK_V2-1 (SB22.2), GPIO_&_Arduino_ Connectors (CN16.3)
PA0_WKUP: Power_PMIC (U4.43), MPU_12x12 (U13.AB3)
PA13: MPU_12x12 (U13.N2), Peripherals (B4.1 B4.2 LD6.2)
PA14: MPU_12x12 (U13.T2), Peripherals (B3.1 B3.2 LD5.2)
PMIC_WAKEUP: Power_PMIC (U4.2), MPU_12x12 (U13.K2)
SAI2_FSA: MPU_12x12 (SB1.1), AUDIO (U20.1)
SAI2_MCLKA: MPU_12x12 (U13.D6), AUDIO (U20.30)
SAI2_SCKA: MPU_12x12 (SB3.1), AUDIO (U20.31)
SAI2_SDA: MPU_12x12 (SB2.1), AUDIO (U20.32)
SAI2_SDB: MPU_12x12 (SB4.1), AUDIO (U20.29)
SDMMC1_CK: MPU_12x12 (U13.D13), Peripherals (CN15.5 R19.1 U10.2 U10.9)
SDMMC1_CMD: MPU_12x12 (U13.D12), Peripherals (CN15.3 R25.1 U10.1 U10.10)
SDMMC1_D0: MPU_12x12 (U13.D18), Peripherals (CN15.7 R16.1 U26.4 U26.7)
SDMMC1_D1: MPU_12x12 (U13.D17), Peripherals (CN15.8 R14.1 U26.5 U26.6)
SDMMC1_D2: MPU_12x12 (U13.D15), Peripherals (CN15.1 R33.1 U26.1 U26.10)
SDMMC1_D3: MPU_12x12 (U13.D16), Peripherals (CN15.2 R28.1 U26.2 U26.9)
SDMMC2_CK: MPU_12x12 (U13.C9), WLAN_BLUETOOTH (TP25.1 U8.20)
SDMMC2_CMD: MPU_12x12 (U13.A10), WLAN_BLUETOOTH (R26.2 U8.22)
SDMMC2_D0: MPU_12x12 (U13.C13), WLAN_BLUETOOTH (R22.2 U8.24)
SDMMC2_D1: MPU_12x12 (U13.B12), WLAN_BLUETOOTH (R17.2 U8.26)
SDMMC2_D2: MPU_12x12 (U13.A11), WLAN_BLUETOOTH (R27.2 U8.23)
SDMMC2_D3: MPU_12x12 (U13.B13), WLAN_BLUETOOTH (R20.2 U8.25)
STLINK_SWCLK: MPU_12x12 (TP5.1 U13.B20), ST_LINK_V2-1 (SB20.2)
STLINK_SWDIO: MPU_12x12 (TP3.1 U13.C20), ST_LINK_V2-1 (SB17.2)
STUSB1600_IRQOUTn: MPU_12x12 (U13.P4), USB_Host_Hub&TypeC_DRP (U12.9)
UART4_RX: MPU_12x12 (U13.Y16), ST_LINK_V2-1 (R77.2)
UART4_TX: MPU_12x12 (U13.Y7), ST_LINK_V2-1 (R72.1)
USART2_CTS: MPU_12x12 (U13.D14), WLAN_BLUETOOTH (U8.5)
USART2_RTS: MPU_12x12 (U13.B6), WLAN_BLUETOOTH (U8.4)
USART2_RX: MPU_12x12 (U13.D2), WLAN_BLUETOOTH (TP27.1 U8.3)
USART2_TX: MPU_12x12 (U13.A7), WLAN_BLUETOOTH (TP28.1 U8.2)
USB1_N: MPU_12x12 (U13.AB17), USB_Host_Hub&TypeC_DRP (U7.30)
USB1_P: MPU_12x12 (U13.AC17), USB_Host_Hub&TypeC_DRP (U7.31)
USB2_N: MPU_12x12 (U13.AB16), USB_Host_Hub&TypeC_DRP (U29.2)
USB2_P: MPU_12x12 (U13.AC16), USB_Host_Hub&TypeC_DRP (U29.1)
USB_PWR_CC1: Power_PMIC (R49.2), MPU_12x12 (U13.V4)
USB_PWR_CC2: Power_PMIC (R56.2), MPU_12x12 (U13.V3)
uSD_DETECT: MPU_12x12 (U13.D11), Peripherals (R13.1)
WL_HOST_WAKE: MPU_12x12 (U13.B8), WLAN_BLUETOOTH (U8.27)
WL_REG_ON: MPU_12x12 (U13.B3), WLAN_BLUETOOTH (TP24.1 U8.28)

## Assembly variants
DK2: not fitted C8 C19 C24 C34 C87 C88 CN12 R9 R12 R32 R69 R73 R74 R78 R127 R134 R140 SB7 SB8 SB11 SB12 SB13 SB14 SB15 SB16 SB18 SB23 SB25
DK1: not fitted C8 C19 C24 C28 C29 C34 C37 C45 C87 C88 CN12 CN18 L1 L4 R9 R12 R17 R20 R22 R26 R27 R32 R69 R73 R74 R78 SB7 SB8 SB11 SB12 SB13 SB14 SB15 SB16 SB18 SB23 SB25 U8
